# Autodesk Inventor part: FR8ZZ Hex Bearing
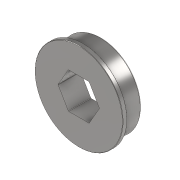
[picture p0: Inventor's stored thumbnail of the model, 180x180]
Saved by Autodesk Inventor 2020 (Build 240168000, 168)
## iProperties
Created: 2020-01
Part Number: FR8ZZ Hex Bearing
Material: Steel, Carbon
Document SubType Name: Modeling
Designer: woodk
Density: 7.85 g/cm^3
Appearance: Semi-Polished
Vendor: KoP
Mass: 32.4776 g
Surface Area: 23.3403 cm^2
Volume: 4.13727 cm^3
Author: woodk
Revision Number: ANY
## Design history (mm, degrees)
fillet "Fillet2"
body "Solid1"
